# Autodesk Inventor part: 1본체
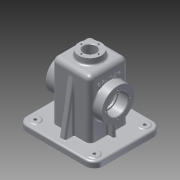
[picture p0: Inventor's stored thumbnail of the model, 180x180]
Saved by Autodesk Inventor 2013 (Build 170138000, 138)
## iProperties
Created: 2016-01
Part Number: 1본체
Material: 알루미늄 6061
Document SubType Name: Modeling
Designer: Administrator
Density: 2.71 g/cm^3
Mass: 867.692 g
Surface Area: 918.115 cm^2
Volume: 320.182 cm^3
Author: Administrator
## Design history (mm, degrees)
sketch "스케치1"
  geometry: L1 (-65, 57.5)-(65, 57.5); L2 (65, 57.5)-(65, -57.5); L3 (65, -57.5)-(-65, -57.5); L4 (-65, -57.5)-(-65, 57.5); 3 further points
  constraints: 8 end point, 2 midpoint, 2 parallel, 1 horizontal, 1 horizontal alignment, 1 perpendicular, 1 vertical alignment
  dimensions: "d0" = 130 distance of L1.start L1.end; "d2" = 115 distance of L1.end L2.end
extrude "돌출1" new body sketch "스케치1" distance "d3" = 10; taper "d4" = 0 deg
fillet "모깎기1" dims "d5" = 15
sketch "스케치2"
  geometry: L1 (-60, -52.5)-(60, -52.5); L2 (60, -52.5)-(60, 52.5); L3 (60, 52.5)-(-60, 52.5); L4 (-60, 52.5)-(-60, -52.5); 3 further points
  constraints: 8 end point, 2 midpoint, 2 parallel, 1 horizontal, 1 horizontal alignment, 1 perpendicular, 1 vertical alignment
  dimensions: "d6" = 105 distance of L3.end L1.start; "d8" = 120 distance of L2.end L3.end
extrude "돌출2" join sketch "스케치2" distance "d9" = 2; taper "d10" = 0 deg
fillet "모깎기2" dims "d11" = 10
sketch "스케치3"
  geometry: C1 r 7.5 at (-50, 42.5); C2 r 7.5 at (-50, -42.5); C3 r 7.5 at (50, -42.5); C4 r 7.5 at (50, 42.5); A1 r 15 centre (50, 42.5) between (65, 42.5) and (50, 57.5) reference; A2 r 15 centre (-50, 42.5) between (-50, 57.5) and (-65, 42.5) reference; A3 r 15 centre (-50, -42.5) between (-65, -42.5) and (-50, -57.5) reference; A4 r 15 centre (50, -42.5) between (50, -57.5) and (65, -42.5) reference; 1 further point
  constraints: 4 centre point, 4 coincident
  dimensions: "d12" = 15 diameter of C1; "d13" = 15 diameter of C2; "d14" = 15 diameter of C3; "d15" = 15 diameter of C4
extrude "돌출3" join sketch "스케치3" distance "d16" = 1; taper "d17" = 0 deg
hole "구멍1" diameter "d20" = 5; stored, may be unused: countersink angle "d24" = 90 deg, drill point angle "d26" = 118 deg; dims "d18" = 10, "d19" = 10, "d21" = 6, "d22" = 4, "d23" = 2, "d25" = 8
hole "구멍2" diameter "d29" = 5; stored, may be unused: countersink angle "d33" = 90 deg, drill point angle "d35" = 118 deg; dims "d27" = 10, "d28" = 10, "d30" = 6, "d31" = 4, "d32" = 2, "d34" = 8
hole "구멍3" diameter "d38" = 5; stored, may be unused: countersink angle "d42" = 90 deg, drill point angle "d44" = 118 deg; dims "d36" = 10, "d37" = 10, "d39" = 6, "d40" = 4, "d41" = 2, "d43" = 8
hole "구멍4" diameter "d47" = 5; stored, may be unused: countersink angle "d51" = 90 deg, drill point angle "d53" = 118 deg; dims "d45" = 10, "d46" = 10, "d48" = 6, "d49" = 4, "d50" = 2, "d52" = 8
sketch "스케치4"
  geometry: L1 (-32.5, 32.5)-(32.5, 32.5); L2 (32.5, 32.5)-(32.5, -32.5); L3 (32.5, -32.5)-(-32.5, -32.5); L4 (-32.5, -32.5)-(-32.5, 32.5); 3 further points
  constraints: 8 end point, 2 midpoint, 2 parallel, 1 horizontal, 1 horizontal alignment, 1 perpendicular, 1 vertical alignment
  dimensions: "d54" = 65 distance of L1.start L1.end; "d56" = 65 distance of L1.end L2.end
extrude "돌출4" join sketch "스케치4" distance "d57" = 98; taper "d58" = 0 deg
sketch "스케치6"
  geometry: C1 r 20 at (0, 0); 1 further point
  constraints: 2 coincident, 1 centre point
  dimensions: "d63" = 40 diameter of C1
extrude "돌출6" join sketch "스케치6" distance "d64" = 10; taper "d65" = -5 deg
fillet "모깎기3" dims "d66" = 8
fillet "모깎기4" dims "d67" = 8
sketch "스케치12"
  geometry: L1 (57.5, 10)-(57.5, 0) reference; L2 (57.5, 0)-(52.5, 0) reference; L3 (52.5, 0)-(52.5, -2) reference; L4 (52.5, -2)-(-52.5, -2) reference; L5 (-52.5, -2)-(-52.5, 0) reference; L6 (-52.5, 0)-(-57.5, 0) reference; L7 (-57.5, 0)-(-57.5, 10) reference; L8 (-57.5, 10)-(-32.5, 10) reference; L9 (-32.5, 10)-(-32.5, 100) reference; L10 (-24.5, 108)-(-20, 108) reference; L11 (-20, 108)-(-19.125, 118) reference; L12 (-19.125, 118)-(19.125, 118) reference; L13 (19.125, 118)-(20, 108) reference; L14 (20, 108)-(24.5, 108) reference; L15 (32.5, 100)-(32.5, 10) reference; L16 (32.5, 10)-(57.5, 10) reference; L17 (-31.102, 103)-(-47.5, 10); L18 (-31.102, 103)-(-31.102, 10); L19 (42.5, 10)-(-42.5, 10) reference; L20 (-57.5, 0)-(-57.5, 10) reference; A1 r 8 centre (-24.5, 100) between (-24.5, 108) and (-32.5, 100) reference; A2 r 8 centre (24.5, 100) between (32.5, 100) and (24.5, 108) reference; 1 further point
  constraints: 4 end point, 2 point on line, 1 vertical
  dimensions: "d122" = 10 distance of L17.end L7.end; "d123" = 10 deg angle of L17 L20; "d124" = 93 distance of L17.start L18.end
extrude "돌출9" join sketch "스케치12" stored distance "d125" = 10; taper "d126" = 0 deg
sketch "스케치7"
  geometry: L1 (27.5, -27.5)-(-27.5, -27.5); L2 (-27.5, -27.5)-(-27.5, 27.5); L3 (-27.5, 27.5)-(27.5, 27.5); L4 (27.5, 27.5)-(27.5, -27.5); 3 further points
  constraints: 8 end point, 2 midpoint, 2 parallel, 1 horizontal, 1 horizontal alignment, 1 perpendicular, 1 vertical alignment
  dimensions: "d68" = 55 distance of L1.end L2.end; "d70" = 55 distance of L1.start L1.end
extrude "돌출7" cut sketch "스케치7" distance "d71" = 105; taper "d72" = 0 deg
fillet "모깎기5" dims "d73" = 3
fillet "모깎기6" dims "d74" = 3
hole "구멍5" diameter "d77" = 21; stored, may be unused: countersink angle "d81" = 90 deg, drill point angle "d83" = 118 deg; dims "d75" = 10, "d76" = 10, "d78" = 6, "d79" = 4, "d80" = 2, "d82" = 8
sketch "스케치8"
  geometry: C1 r 27.5 at (-50.689, 24.5); 1 further point
  constraints: 1 centre point
  dimensions: "d84" = 55 diameter of C1
extrude "돌출8" join sketch "스케치8" distance "d85" = 15; taper "d86" = 0 deg
hole "구멍6" diameter "d89" = 30; stored, may be unused: countersink angle "d93" = 90 deg, drill point angle "d95" = 0 deg; dims "d87" = 10, "d88" = 10, "d90" = 6, "d91" = 35, "d92" = 17, "d94" = 20
sketch "스케치9"
  geometry: C1 r 17.5 at (0, 0) reference; 2 further points
  constraints: 1 horizontal alignment
  dimensions: "d96" = 21 distance of C1.centre point (21, 0)
hole "구멍7" sketch "스케치9" at (21, 0) diameter "d97" = 3.242; stored, may be unused: countersink angle "d101" = 90 deg, drill point angle "d103" = 118 deg; dims "d98" = 8, "d99" = 35, "d100" = 17, "d102" = 10
sketch "스케치10"
  geometry: C1 r 10.5 at (0, 0) reference; 1 further point
  constraints: 1 horizontal alignment
  dimensions: "d107" = 14.5 distance of C1.centre point (-14.5, 0)
hole "구멍8" sketch "스케치10" at (-14.5, 0) diameter "d108" = 2.459; stored, may be unused: countersink angle "d112" = 90 deg, drill point angle "d114" = 118 deg; dims "d109" = 7, "d110" = 35, "d111" = 17, "d113" = 9
sketch "스케치14"
  geometry: L1 (-18, 5.375)-(-18, 43.625) reference; A1 r 27.5 centre (39.311, 24.5) between (26.821, 49) and (26.821, 0) reference; 2 further points
  constraints: 1 horizontal alignment, 1 other
  dimensions: "d131" = 27 distance from line of L1 point (9, 24.5)
feature "엠보싱1" sketch "스케치14" dims "d132" = 0.5, "d133" = 0
chamfer "모따기1" distance "d134" = 1; stored, may be unused: second distance "d135" = 2, angle "d136" = 45 deg
fillet "모깎기7" dims "d137" = 0.3
fillet "모깎기8" dims "d138" = 3
fillet "모깎기9" dims "d139" = 3
fillet "모깎기10" dims "d140" = 3
sketch "스케치15"
  geometry: L1 (-27.5, 100)-(-27.5, 75.689) reference; L2 (-27.5, 75.689)-(-30.5, 75.689) reference; L3 (-30.5, 75.689)-(-30.5, 77.889) reference; L4 (-30.8, 78.189)-(-46.5, 78.189) reference; L5 (-46.5, 78.189)-(-47.5, 79.189) reference; L6 (-47.5, 79.189)-(-47.5, 80.068) reference; L7 (-47.5, 80.068)-(-37.5, 80.068) reference; L8 (-37.5, 80.068)-(-36.526, 81.689) reference; L9 (-36.526, 81.689)-(-37.5, 83.31) reference; L10 (-37.5, 83.31)-(-47.5, 83.31) reference; L11 (-47.5, 83.31)-(-47.5, 88.189) reference; L12 (-47.5, 88.189)-(-32.5, 88.189) reference; L13 (-32.5, 88.189)-(-32.5, 92.971) reference; L14 (-32.5, 92.971)-(-33, 92.971) reference; L15 (-33, 92.971)-(-33, 93.385) reference; L16 (-33, 93.385)-(-32.5, 93.385) reference; L17 (-32.5, 93.385)-(-32.5, 100) reference; L18 (-24.5, 108)-(-20, 108) reference; L19 (-20, 108)-(-19.125, 118) reference; L20 (-19.125, 118)-(-15.73, 118) reference; L21 (-15.73, 118)-(-15.73, 109) reference; L22 (-15.73, 109)-(-14.5, 108.261) reference; L23 (-14.5, 108.261)-(-13.271, 109) reference; L24 (-13.271, 109)-(-13.271, 118) reference; L25 (-13.271, 118)-(-11.5, 118) reference; L26 (-11.5, 118)-(-10.5, 117) reference; L27 (-10.5, 117)-(-10.5, 103) reference; L28 (-10.5, 103)-(-24.5, 103) reference; L29 (24.5, 103)-(10.5, 103) reference; L30 (10.5, 103)-(10.5, 117) reference; L31 (10.5, 117)-(11.5, 118) reference; L32 (11.5, 118)-(13.271, 118) reference; L33 (13.271, 118)-(13.271, 109) reference; L34 (13.271, 109)-(14.5, 108.261) reference; L35 (14.5, 108.261)-(15.73, 109) reference; L36 (15.73, 109)-(15.73, 118) reference; L37 (15.73, 118)-(19.125, 118) reference; L38 (19.125, 118)-(20, 108) reference; L39 (20, 108)-(24.5, 108) reference; L40 (32.5, 100)-(32.5, 88.189) reference; L41 (32.5, 88.189)-(47.5, 88.189) reference; L42 (47.5, 88.189)-(47.5, 83.31) reference; L43 (47.5, 83.31)-(37.5, 83.31) reference; L44 (37.5, 83.31)-(36.526, 81.689) reference; L45 (36.526, 81.689)-(37.5, 80.068) reference; L46 (37.5, 80.068)-(47.5, 80.068) reference; L47 (47.5, 80.068)-(47.5, 79.189) reference; L48 (47.5, 79.189)-(46.5, 78.189) reference; L49 (46.5, 78.189)-(30.8, 78.189) reference; L50 (30.5, 77.889)-(30.5, 75.689) reference; L51 (30.5, 75.689)-(27.5, 75.689) reference; L52 (27.5, 75.689)-(27.5, 100) reference; L53 (-60, -2)-(-60, 0) reference; L54 (-60, 0)-(-65, 0) reference; L55 (-65, 0)-(-65, 7) reference; L56 (-62, 10)-(-32.5, 10) reference; L57 (-32.5, 10)-(-32.5, 33.189) reference; L58 (-32.5, 33.189)-(-47.5, 33.189) reference; L59 (-47.5, 33.189)-(-47.5, 38.068) reference; L60 (-47.5, 38.068)-(-37.5, 38.068) reference; L61 (-37.5, 38.068)-(-36.526, 39.689) reference; L62 (-36.526, 39.689)-(-37.5, 41.31) reference; L63 (-37.5, 41.31)-(-47.5, 41.31) reference; L64 (-47.5, 41.31)-(-47.5, 42.189) reference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; A1 r 3 centre (-24.5, 100) between (-24.5, 103) and (-27.5, 100) reference; A2 r 0.3 centre (-30.8, 77.889) between (-30.5, 77.889) and (-30.8, 78.189) reference; A3 r 8 centre (-24.5, 100) between (-24.5, 108) and (-32.5, 100) reference; A4 r 3 centre (24.5, 100) between (27.5, 100) and (24.5, 103) reference; A5 r 8 centre (24.5, 100) between (32.5, 100) and (24.5, 108) reference; A6 r 0.3 centre (30.8, 77.889) between (30.8, 78.189) and (30.5, 77.889) reference; A7 r 3 centre (-62, 7) between (-62, 10) and (-65, 7) reference; A8 r 0.3 centre (-30.8, 43.489) between (-30.8, 43.189) and (-30.5, 43.489) reference; A9 r 0.3 centre (30.8, 43.489) between (30.5, 43.489) and (30.8, 43.189) reference; A10 r 3 centre (62, 7) between (65, 7) and (62, 10) reference; 1 further point
  constraints: 2 end point, 2 point on line, 1 vertical
  dimensions: "d142" = 15 distance between parallel lines of L89 L69
feature "리브1" sketch "스케치15" dims "d143" = 1, "d144" = 6, "d145" = 0, "d146" = 0, "d147" = 1, "d148" = 1
fillet "모깎기11" dims "d149" = 3
fillet "모깎기12" dims "d150" = 3
fillet "모깎기13" dims "d151" = 3
fillet "모깎기14" dims "d152" = 1
fillet "모깎기15" dims "d153" = 3
fillet "모깎기16" dims "d154" = 3
node "솔리드1"
mirror "대칭3"
mirror "대칭1"
pattern_circular "원형 패턴1" dims angle "d105" = 360 deg
mirror "대칭2"
pattern_circular "원형 패턴2" dims angle "d116" = 360 deg
mirror "대칭4"
node "절단 모서리 투영2"
node "절단 모서리 투영4"
